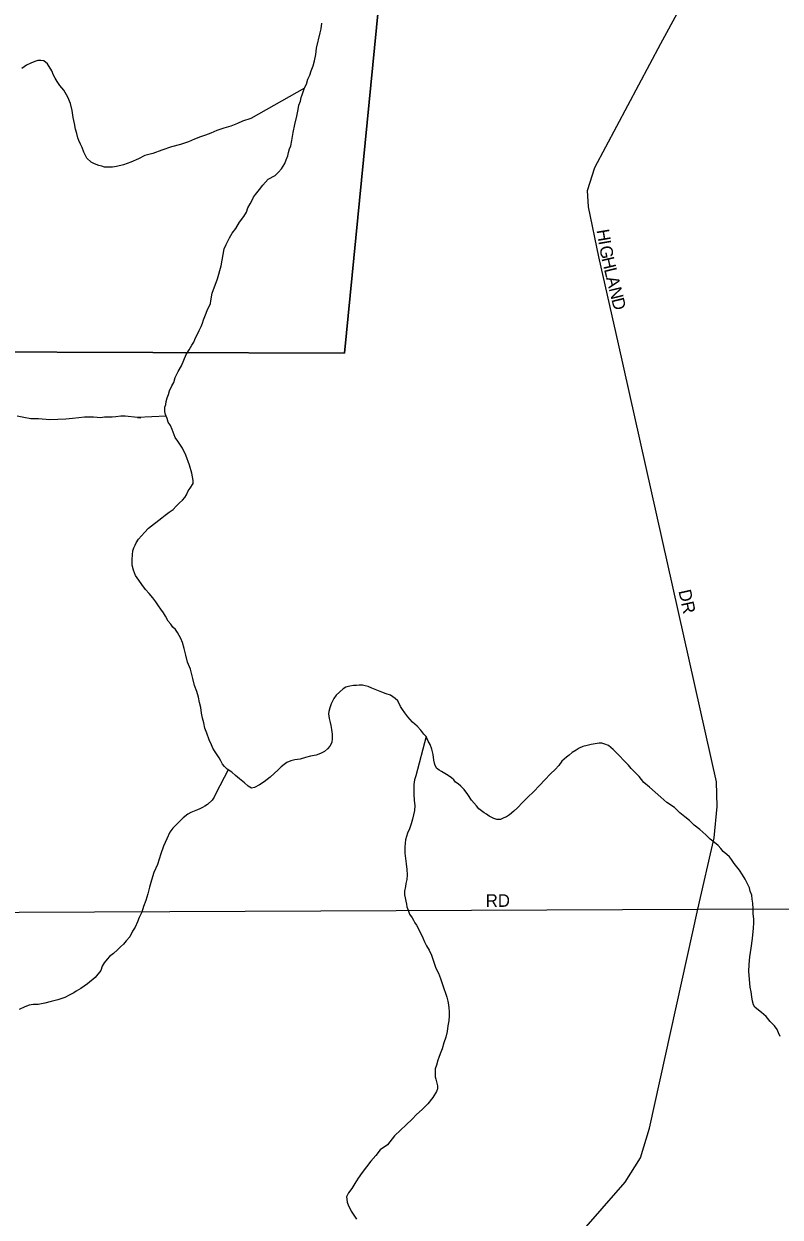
# Model space of a CAD drawing. Extents: x 2010165 to 2382125, y 1060529 to 1407316.
# Drawn here: x 2203170 to 2206176, y 1204883 to 1209626 of the extents above; entities that cross this region are included whole.
import ezdxf

# ---------------------------------------------------------------- set-up
doc = ezdxf.new("R2010")
doc.units = 0
for name, color, linetype in [('GM_X_City_Street', 7, 'Continuous'), ('GM_X_City_Street_Text', 7, 'Continuous'), ('GM_X_Corporation', 7, 'Continuous'), ('GM_X_Minor_River', 7, 'Continuous')]:
    doc.layers.add(name, color=color, linetype=linetype)

msp = doc.modelspace()

# ---------------------------------------------------------------- linework, layer by layer
at = {"layer": 'GM_X_City_Street'}
for points in [[(2204477.5, 1203768.7), (2204517.1, 1203815.6), (2205378, 1204812.6), (2205560.9, 1205022), (2205621, 1205118.3), (2205657.1, 1205237.2), (2205848.8, 1206107.4), (2205913.8, 1206390.7), (2205926.1, 1206514.8), (2205923.3, 1206613), (2205534.4, 1208354.5), (2205455.5, 1208700.4), (2205414.2, 1208898.4), (2205410.7, 1208963.9), (2205440, 1209055.1), (2205701.7, 1209548.4), (2205904.8, 1209922.1), (2205958.6, 1210019.5), (2206002.3, 1210073.5), (2206063.1, 1210121.7), (2206236.8, 1210203.6), (2206451.2, 1210308.8), (2206573.3, 1210367.5)], [(2196693.1, 1206074.3), (2200608.2, 1206079.6), (2202550.7, 1206093.1), (2205848.8, 1206107.4), (2208487.9, 1206109.2)]]:
    msp.add_lwpolyline(points, dxfattribs=at)
at = {"layer": 'GM_X_Corporation'}
for points in [[(2204447.2, 1221938.7), (2204662.3, 1210529.8), (2204445.3, 1208317.3), (2199872.3, 1208332.6), (2199834.9, 1208326), (2199654.4, 1208314.4), (2199497, 1208304.3), (2197215.9, 1208288.2), (2196205.1, 1208275.6), (2196632.3, 1194905.5), (2192680.8, 1194838.8), (2189318.2, 1194759.1), (2187205, 1194725.9), (2187027.1, 1208132.6), (2187013.9, 1213879), (2186978.3, 1216841.2), (2186941.3, 1219753.4), (2186933.5, 1220238.7), (2186923.4, 1220744.1), (2186878.7, 1221701)], [(2225489.9, 1195453.9), (2213202.5, 1195199), (2210879.2, 1195154.6), (2209126.8, 1195115.5), (2208833.2, 1195110.6), (2205335.3, 1195051.8), (2197309.3, 1194916.9), (2196632.3, 1194905.5), (2196205.1, 1208275.6), (2197215.9, 1208288.2), (2199497, 1208304.3), (2199654.4, 1208314.4), (2199834.9, 1208326), (2199872.3, 1208332.6), (2204445.3, 1208317.3), (2204662.3, 1210529.8), (2204447.2, 1221938.7)]]:
    msp.add_lwpolyline(points, dxfattribs=at)
at = {"layer": 'GM_X_Minor_River'}
for points in [[(2204060.3, 1208894.6), (2204069.8, 1208910.9), (2204077.5, 1208925.1), (2204083.2, 1208937.3), (2204090.9, 1208947.6), (2204106.4, 1208968), (2204120, 1208984.5), (2204141.4, 1209009.1), (2204169.1, 1209023.9), (2204182.8, 1209036.3), (2204194.4, 1209050.7), (2204207.9, 1209071.1), (2204213.5, 1209085.3), (2204219.1, 1209101.5), (2204222.7, 1209115.6), (2204226.4, 1209129.8), (2204232, 1209142), (2204235.5, 1209162.1), (2204240.6, 1209194.4), (2204247.8, 1209226.7), (2204254.9, 1209259), (2204260.3, 1209285.3), (2204263.8, 1209303.4), (2204269.3, 1209319.6), (2204273, 1209333.8), (2204276.7, 1209343.9), (2204280.4, 1209356.1), (2204286, 1209372.2), (2204293.6, 1209386.5), (2204299.1, 1209406.7), (2204306.7, 1209423), (2204312.2, 1209439.2), (2204319.7, 1209459.5), (2204325.2, 1209479.7), (2204330.5, 1209503.9), (2204333.8, 1209530.1), (2204348.2, 1209590.7), (2204351.8, 1209606.8), (2204355.2, 1209629)], [(2204285.3, 1209370.3), (2204072.7, 1209250.2), (2204038.9, 1209239.3), (2204019.1, 1209230.8), (2203993.3, 1209220), (2203965.5, 1209211.3), (2203937.6, 1209202.5), (2203913.9, 1209191.8), (2203892, 1209183.2), (2203872.2, 1209176.7), (2203848.3, 1209168), (2203824.6, 1209157.4), (2203792.8, 1209146.5), (2203756.9, 1209137.5), (2203719.2, 1209124.5), (2203683.4, 1209111.5), (2203651.6, 1209102.7), (2203625.9, 1209089.9), (2203596.1, 1209077.1), (2203566.3, 1209066.3), (2203538.4, 1209059.5), (2203522.5, 1209057.1), (2203500.4, 1209056.5), (2203490.4, 1209056.3), (2203480.3, 1209060), (2203468.1, 1209063.7), (2203458, 1209067.5), (2203447.9, 1209071.2), (2203437.7, 1209077), (2203421.2, 1209092.6), (2203415, 1209102.5), (2203408.6, 1209116.4), (2203402.1, 1209134.2), (2203395.7, 1209148.1), (2203389.3, 1209162), (2203385, 1209173.9), (2203380.5, 1209189.9), (2203376, 1209207.8), (2203371.4, 1209229.8), (2203366.8, 1209253.8), (2203362, 1209281.8), (2203355.2, 1209309.7), (2203344.5, 1209335.5), (2203329.7, 1209363.2), (2203313.2, 1209380.8), (2203302.7, 1209396.6), (2203294.3, 1209410.5), (2203288, 1209422.3), (2203281.5, 1209440.2), (2203264.7, 1209467.9), (2203250.3, 1209479.6), (2203238.3, 1209481.3), (2203226.3, 1209480.9), (2203214.3, 1209476.6), (2203198.5, 1209470.2), (2203180.6, 1209461.7), (2203162.9, 1209449.2)], [(2203813.6, 1207117.5), (2203806.9, 1207143.4), (2203800.2, 1207167.3), (2203793.7, 1207183.2), (2203787.4, 1207195.1), (2203781.1, 1207207), (2203772.7, 1207218.8), (2203762.4, 1207228.6), (2203754.1, 1207240.4), (2203743.8, 1207252.2), (2203733.2, 1207272), (2203724.8, 1207285.8), (2203714.4, 1207299.6), (2203706, 1207313.4), (2203695.5, 1207329.2), (2203683.1, 1207344.9), (2203668.6, 1207362.6), (2203654.1, 1207378.3), (2203639.5, 1207398), (2203627, 1207415.7), (2203614.5, 1207433.4), (2203605.9, 1207455.3), (2203601.4, 1207475.3), (2203600.8, 1207497.3), (2203602.3, 1207515.4), (2203603.8, 1207531.5), (2203607.5, 1207543.7), (2203613.3, 1207553.9), (2203617, 1207564), (2203626.6, 1207578.3), (2203638.3, 1207590.7), (2203650, 1207605), (2203665.6, 1207621.5), (2203718.6, 1207663), (2203732.4, 1207673.4), (2203748.1, 1207685.9), (2203763.8, 1207696.3), (2203775.5, 1207708.7), (2203789.2, 1207723.1), (2203800.9, 1207733.4), (2203810.7, 1207743.7), (2203816.4, 1207753.9), (2203824, 1207770.2), (2203831.7, 1207780.4), (2203843.3, 1207798.8), (2203842.9, 1207810.8), (2203838.1, 1207840.8), (2203829.2, 1207872.7), (2203814.1, 1207912.5), (2203801.3, 1207940.2), (2203790.9, 1207956), (2203782.5, 1207967.8), (2203772.1, 1207981.6), (2203759.2, 1208013.4), (2203752.8, 1208029.3), (2203744.4, 1208043.1), (2203740, 1208057.1), (2203733.6, 1208073), (2203731.3, 1208084.9), (2203730.8, 1208103), (2203734.5, 1208113.1), (2203736.2, 1208125.2), (2203739.8, 1208139.4), (2203745.4, 1208153.6), (2203749.1, 1208167.7), (2203758.5, 1208188), (2203766.2, 1208200.3), (2203771.7, 1208220.5), (2203783.1, 1208244.9), (2203796.5, 1208267.3), (2203805.9, 1208289.6), (2203815.3, 1208312), (2203826.9, 1208330.3), (2203838.4, 1208348.7), (2203846.1, 1208361), (2203849.8, 1208371.1), (2203855.5, 1208383.3), (2203861.2, 1208395.5), (2203866.9, 1208407.7), (2203874.5, 1208423.9), (2203880.2, 1208436.1), (2203883.8, 1208450.3), (2203889.5, 1208462.5), (2203895.1, 1208476.7), (2203900.7, 1208490.9), (2203906.4, 1208503.1), (2203912.1, 1208515.3), (2203913.8, 1208525.4), (2203919, 1208555.6), (2203939.6, 1208612.3), (2203954.2, 1208664.9), (2203966.4, 1208731.5), (2203973.9, 1208749.8), (2203979.7, 1208760), (2203987.3, 1208776.2), (2203998.8, 1208794.6), (2204012.3, 1208813), (2204027.7, 1208837.5), (2204045.2, 1208860), (2204054.7, 1208878.4), (2204060.3, 1208894.6)], [(2203736.2, 1208066.5), (2203621.6, 1208062), (2203635.7, 1208060.3), (2203621.6, 1208062), (2203573.3, 1208066.7), (2203555.3, 1208066.3), (2203535.3, 1208063.7), (2203521.3, 1208063.4), (2203505.2, 1208062.9), (2203491.2, 1208062.6), (2203475.2, 1208060.1), (2203461.2, 1208061.8), (2203447.1, 1208063.4), (2203429, 1208062.9), (2203411, 1208062.5), (2203389, 1208059.9), (2203363, 1208057.2), (2203337, 1208054.5), (2203305, 1208053.7), (2203272.9, 1208052.8), (2203228.7, 1208055.7), (2203198.6, 1208056.9), (2203170.4, 1208062.2), (2203144.2, 1208067.5)], [(2204896.2, 1206605.9), (2204886, 1206611.6), (2204879.8, 1206621.5), (2204869.5, 1206629.3), (2204857.2, 1206639), (2204843, 1206646.6), (2204830.7, 1206654.4), (2204820.6, 1206660.1), (2204810.3, 1206667.9), (2204803.9, 1206681.8), (2204799.4, 1206699.7), (2204796.8, 1206721.7), (2204792.2, 1206743.7), (2204785.7, 1206761.6), (2204777.3, 1206775.4), (2204768.8, 1206793.3), (2204760.6, 1206803.1), (2204748.1, 1206818.8), (2204733.6, 1206834.5), (2204715.2, 1206850.1), (2204696.5, 1206871.7), (2204684.1, 1206887.4), (2204675.7, 1206901.2), (2204667.3, 1206913.1), (2204656.7, 1206934.8), (2204646.4, 1206944.6), (2204628, 1206958.2), (2204609.8, 1206963.7), (2204593.6, 1206969.3), (2204567.3, 1206980.7), (2204553.1, 1206986.3), (2204538.9, 1206992), (2204526.7, 1206995.7), (2204516.7, 1206997.4), (2204502.6, 1206997.1), (2204492.6, 1206996.8), (2204480.6, 1206996.5), (2204466.6, 1206994.1), (2204450.7, 1206989.7), (2204438.8, 1206983.3), (2204411.4, 1206958.5), (2204401.8, 1206944.2), (2204392.3, 1206923.9), (2204386.7, 1206907.7), (2204383.1, 1206893.5), (2204381.4, 1206883.5), (2204383.9, 1206865.5), (2204388.3, 1206849.5), (2204390.6, 1206837.5), (2204393.1, 1206821.5), (2204395.6, 1206803.5), (2204396.1, 1206785.5), (2204394.5, 1206769.4), (2204386.9, 1206755.1), (2204377.1, 1206744.8), (2204365.4, 1206734.5), (2204349.5, 1206726), (2204331.7, 1206719.6), (2204309.7, 1206715), (2204289.8, 1206710.4), (2204267.9, 1206703.8), (2204247.9, 1206701.3), (2204232, 1206696.8), (2204216.2, 1206690.4), (2204204.4, 1206682.1), (2204192.5, 1206673.7), (2204180.8, 1206661.4), (2204165.2, 1206646.9), (2204149.5, 1206632.5), (2204126, 1206613.8), (2204106.3, 1206601.2), (2204086.5, 1206590.6), (2204074.5, 1206588.3), (2204062.3, 1206596), (2204047.9, 1206609.7), (2204027.4, 1206625.2), (2204011, 1206638.9), (2203996.6, 1206652.5), (2203978.2, 1206664.1), (2203968, 1206673.9), (2203959.7, 1206683.7), (2203953.3, 1206697.6), (2203946.9, 1206709.4), (2203928.1, 1206737.1), (2203921.9, 1206746.9), (2203915.5, 1206760.8), (2203906.9, 1206780.7), (2203898.2, 1206806.5), (2203889.6, 1206826.4), (2203885, 1206848.3), (2203880.5, 1206866.3), (2203876, 1206886.2), (2203873.4, 1206908.3), (2203868.8, 1206928.2), (2203864.2, 1206950.2), (2203857.6, 1206972.1), (2203848.9, 1206995.9), (2203842.2, 1207023.9), (2203833.1, 1207061.8), (2203820.3, 1207089.6), (2203813.6, 1207117.5)], [(2204768.8, 1206793.3), (2204728.9, 1206637.6), (2204723.4, 1206621.4), (2204719.8, 1206603.3), (2204720.3, 1206585.2), (2204720.9, 1206565.1), (2204721.6, 1206539.1), (2204724.1, 1206519.1), (2204722.7, 1206498.9), (2204719.1, 1206482.8), (2204715.6, 1206464.6), (2204710, 1206446.4), (2204702.6, 1206426.1), (2204695, 1206409.9), (2204691.4, 1206395.8), (2204687.7, 1206383.6), (2204686.1, 1206369.5), (2204684.5, 1206353.4), (2204685.1, 1206329.3), (2204687.7, 1206309.3), (2204690.3, 1206287.3), (2204692.9, 1206265.3), (2204693.5, 1206243.2), (2204692, 1206225.1), (2204688.4, 1206209), (2204686.7, 1206196.9), (2204683.2, 1206178.7), (2204683.6, 1206164.7), (2204685.9, 1206152.7), (2204688.3, 1206138.7), (2204690.6, 1206126.7), (2204692.9, 1206116.7), (2204697.3, 1206102.8), (2204703.7, 1206086.9), (2204714.1, 1206073.1), (2204718.4, 1206063.2), (2204724.7, 1206053.3), (2204731, 1206043.5), (2204750, 1206007.8), (2204756.4, 1205993.9), (2204762.8, 1205978.1), (2204771.3, 1205962.2), (2204781.8, 1205944.4), (2204790.3, 1205924.6), (2204799, 1205900.7), (2204807.8, 1205872.8), (2204818.3, 1205853), (2204826.9, 1205831.2), (2204833.5, 1205811.3), (2204840, 1205791.4), (2204846.5, 1205773.5), (2204851, 1205757.5), (2204855.4, 1205741.6), (2204857.8, 1205727.6), (2204860.1, 1205715.6), (2204860.6, 1205699.6), (2204861, 1205683.5), (2204859.6, 1205663.4), (2204856.1, 1205643.2), (2204852.7, 1205621.1), (2204847.3, 1205598.8), (2204839.8, 1205576.6), (2204832.5, 1205552.3), (2204825, 1205532), (2204819.4, 1205517.8), (2204815.6, 1205507.7), (2204810.2, 1205487.4), (2204804.5, 1205473.2), (2204804.8, 1205463.2), (2204805.1, 1205453.2), (2204805.4, 1205441.1), (2204807.7, 1205431.2), (2204810, 1205421.2), (2204814.4, 1205405.2), (2204814.7, 1205393.2), (2204811, 1205383.1), (2204795.6, 1205358.6), (2204776.2, 1205334), (2204752.8, 1205311.3), (2204731.3, 1205290.6), (2204713.7, 1205272.1), (2204643.3, 1205206), (2204616.2, 1205171.2), (2204586.7, 1205150.3), (2204569.2, 1205127.8), (2204549.8, 1205105.2), (2204532.3, 1205082.6), (2204514.9, 1205060.1), (2204499.5, 1205037.6), (2204486, 1205017.2), (2204474.5, 1204996.8), (2204460.9, 1204980.4), (2204453.3, 1204964.1), (2204453.6, 1204954.1), (2204455.9, 1204942.1), (2204460.3, 1204928.2), (2204466.7, 1204916.3), (2204470.9, 1204906.4), (2204481.4, 1204890.6), (2204491.8, 1204874.8)], [(2206153.5, 1205643.2), (2206137, 1205660.8), (2206120.4, 1205680.4), (2206101.9, 1205696), (2206089.6, 1205705.7), (2206075.3, 1205717.4), (2206071, 1205727.3), (2206066.6, 1205741.3), (2206064.1, 1205759.3), (2206061.6, 1205779.3), (2206057.1, 1205797.2), (2206051.4, 1205859.3), (2206052.6, 1205887.4), (2206055.8, 1205917.6), (2206060.9, 1205951.9), (2206065.9, 1205990.2), (2206070.8, 1206032.5), (2206072.2, 1206052.6), (2206071.8, 1206068.6), (2206069.3, 1206088.6), (2206068.7, 1206108.7), (2206068.1, 1206130.8), (2206065.7, 1206146.8), (2206063.3, 1206162.8), (2206056.8, 1206178.6), (2206054.4, 1206192.6), (2206046, 1206208.5), (2206037.5, 1206226.3), (2206027, 1206244.1), (2206014.5, 1206261.9), (2206004, 1206275.6), (2205993.6, 1206289.4), (2205983.2, 1206305.2), (2205974.9, 1206315), (2205964.6, 1206324.8), (2205950.3, 1206336.5), (2205939.9, 1206348.2), (2205929.6, 1206360), (2205915.2, 1206371.7), (2205898.8, 1206385.3), (2205880.3, 1206402.9), (2205857.7, 1206424.4), (2205835.1, 1206441.8), (2205816.6, 1206459.4), (2205798.1, 1206475), (2205777.7, 1206490.5), (2205757, 1206512.1), (2205726.4, 1206531.3), (2205701.8, 1206552.8), (2205679.2, 1206572.2), (2205656.6, 1206591.7), (2205634, 1206611.2), (2205615.3, 1206634.8), (2205598.8, 1206652.4), (2205584.4, 1206666.1), (2205574, 1206679.9), (2205561.7, 1206691.6), (2205530.7, 1206722.9), (2205522.5, 1206732.8), (2205512.2, 1206742.5), (2205493.7, 1206758.1), (2205479.5, 1206763.7), (2205467.4, 1206767.4), (2205457.3, 1206767.2), (2205441.4, 1206764.8), (2205425.4, 1206762.3), (2205409.5, 1206757.9), (2205391.5, 1206753.4), (2205377.7, 1206747), (2205365.9, 1206738.7), (2205350.1, 1206730.2), (2205338.3, 1206719.9), (2205326.5, 1206711.5), (2205308.9, 1206695), (2205297.3, 1206678.7), (2205281.7, 1206662.2), (2205264.1, 1206645.7), (2205240.7, 1206621), (2205219.3, 1206598.3), (2205197.8, 1206575.7), (2205172.4, 1206550.9), (2205150.9, 1206530.3), (2205133.4, 1206511.8), (2205117.7, 1206497.3), (2205100.1, 1206482.8), (2205088.3, 1206474.4), (2205078.4, 1206470.1), (2205064.5, 1206463.8), (2205050.5, 1206463.4), (2205038.3, 1206467.1), (2205020, 1206476.6), (2205009.8, 1206484.4), (2204999.6, 1206490.2), (2204989.4, 1206497.9), (2204979.1, 1206505.7), (2204968.8, 1206517.5), (2204950.1, 1206541.1), (2204935.5, 1206562.8), (2204920.9, 1206582.4), (2204906.5, 1206596.1), (2204896.2, 1206605.9)], [(2203982.6, 1206661.3), (2203932.8, 1206566.5), (2203927.1, 1206552.3), (2203919.4, 1206540.1), (2203899.8, 1206523.5), (2203890, 1206517.2), (2203880.1, 1206510.9), (2203870.2, 1206506.7), (2203860.3, 1206502.4), (2203834.5, 1206491.7), (2203822.7, 1206485.3), (2203803, 1206470.8), (2203762, 1206429.6), (2203750.4, 1206413.2), (2203739.1, 1206386.8), (2203725.8, 1206358.3), (2203714.6, 1206327.9), (2203701.7, 1206285.4), (2203686.6, 1206252.9), (2203677.4, 1206222.6), (2203670.1, 1206194.3), (2203662.8, 1206168), (2203655.5, 1206141.7), (2203646.1, 1206117.4), (2203638.7, 1206095.1), (2203629.2, 1206074.8), (2203621.7, 1206056.5), (2203612.2, 1206036.2), (2203602.6, 1206019.8), (2203591.2, 1205997.5), (2203577.6, 1205981.1), (2203565.9, 1205968.7), (2203554.2, 1205958.3), (2203542.5, 1205946), (2203526.8, 1205931.5), (2203511.1, 1205919.1), (2203501.4, 1205908.8), (2203489.7, 1205894.4), (2203482.1, 1205880.2), (2203476.5, 1205864), (2203453.2, 1205835.2), (2203423.8, 1205810.4), (2203396.2, 1205791.6), (2203378.5, 1205781.1), (2203368.6, 1205774.8), (2203352.8, 1205766.4), (2203333, 1205755.8), (2203305.2, 1205747), (2203279.3, 1205740.3), (2203253.4, 1205733.6), (2203227.5, 1205728.9), (2203207.4, 1205728.4), (2203191.5, 1205726), (2203173.6, 1205719.5), (2203151.8, 1205708.9)], [(2206176.7, 1205601.6), (2206170.3, 1205615.5), (2206163.9, 1205629.4), (2206153.5, 1205643.2)]]:
    msp.add_lwpolyline(points, dxfattribs=at)

# ---------------------------------------------------------------- texts
at = {"layer": 'GM_X_City_Street_Text'}
for s, rotation, p in [('H', 279.5306, (2205446.3, 1208805.9)), ('I', 279.4839, (2205453.5, 1208762.6)), ('G', 280.3832, (2205457.3, 1208740)), ('H', 283.2776, (2205465.8, 1208694)), ('L', 283.7686, (2205476, 1208650.7)), ('A', 283.7693, (2205484.4, 1208616.5)), ('N', 283.75, (2205494.9, 1208573.8)), ('D', 283.7693, (2205505.3, 1208531.1)), ('DR', 282.5327, (2205771.7, 1207372.1)), ('RD', 0, (2205005.8, 1206116.6))]:
    msp.add_text(s, height=50, rotation=rotation, dxfattribs=at).set_placement(p)

doc.saveas('drawing.dxf')
